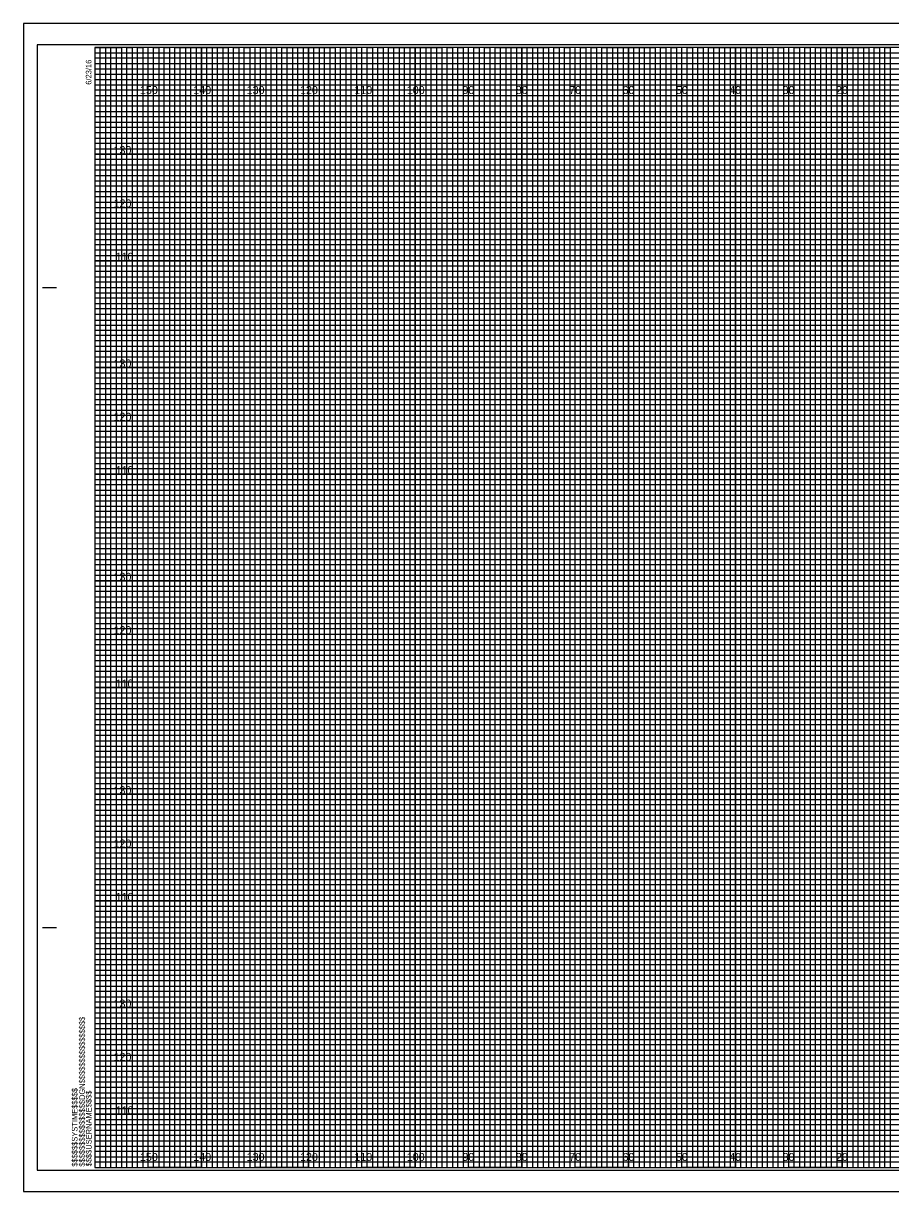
# Model space of a CAD drawing. Extents: x -13 to 323, y -5 to 654.
# Drawn here: x -13.4 to 149.1, y 215.5 to 434.5 of the extents above; entities that cross this region are included whole.
import ezdxf

# ---------------------------------------------------------------- set-up
doc = ezdxf.new("R2010")
doc.units = 0
for name, color, linetype in [('Prop XS Elevation Labels', 7, 'Continuous'), ('Prop XS Offset Labels', 7, 'Continuous'), ('Sheet Cross Section CELL', 7, 'Continuous'), ('Sheet Cross Section Grid Major CELL', 7, 'Continuous'), ('Sheet Cross Section Grid Middle CELL', 7, 'Continuous'), ('Sheet Cross Section Grid Minor 1 CELL', 7, 'Continuous'), ('Sheet Cross Section Grid Minor 2 CELL', 7, 'Continuous'), ('Sheet Cutting Line CELL', 7, 'Continuous'), ('Sheet DOT Grid CELL', 7, 'Continuous'), ('Sheet Plot Border Inside CELL', 7, 'Continuous'), ('Sheet Plot Border Outside CELL', 7, 'Continuous')]:
    doc.layers.add(name, color=color, linetype=linetype)

msp = doc.modelspace()

# ---------------------------------------------------------------- linework, layer by layer
at = {"layer": 'Sheet Cross Section CELL'}
for p, q in [((-9.8, 385), (-7.3, 385)), ((-9.7, 385), (-7.2, 385)), ((-9.8, 265), (-7.3, 265)), ((-9.7, 265), (-7.2, 265)), ((0, 220), (0, 220)), ((0, 220), (0, 220)), ((0, 220), (0, 220)), ((0, 220), (0, 220)), ((0, 220), (0, 220)), ((0, 220), (0, 220)), ((0, 220), (0, 220))]:
    msp.add_line(p, q, dxfattribs=at)
msp.add_lwpolyline([(320, 430), (0, 430), (0, 220), (320, 220)], close=True, dxfattribs=at)
at = {"layer": 'Sheet Cross Section Grid Major CELL'}
for p, q in [((10, 430), (0, 430)), ((10, 220), (10, 430)), ((30, 430), (20, 430)), ((20, 430), (20, 220)), ((30, 220), (30, 430)), ((50, 430), (40, 430)), ((40, 430), (40, 220)), ((50, 220), (50, 430)), ((70, 430), (60, 430)), ((60, 430), (60, 220)), ((70, 220), (70, 430)), ((90, 430), (80, 430)), ((80, 430), (80, 220)), ((90, 220), (90, 430)), ((110, 430), (100, 430)), ((100, 430), (100, 220)), ((110, 220), (110, 430)), ((130, 430), (120, 430)), ((120, 430), (120, 220)), ((130, 220), (130, 430)), ((150, 430), (140, 430)), ((140, 430), (140, 220)), ((20, 220), (10, 220)), ((40, 220), (30, 220)), ((60, 220), (50, 220)), ((80, 220), (70, 220)), ((100, 220), (90, 220)), ((120, 220), (110, 220)), ((140, 220), (130, 220))]:
    msp.add_line(p, q, dxfattribs=at)
for points in [[(0, 420), (320, 420), (320, 410), (0, 410)], [(0, 400), (320, 400), (320, 390), (0, 390)], [(0, 380), (320, 380), (320, 370), (0, 370)], [(0, 360), (320, 360), (320, 350), (0, 350)], [(0, 340), (320, 340), (320, 330), (0, 330)], [(0, 320), (320, 320), (320, 310), (0, 310)], [(0, 300), (320, 300), (320, 290), (0, 290)], [(0, 280), (320, 280), (320, 270), (0, 270)], [(0, 260), (320, 260), (320, 250), (0, 250)], [(0, 240), (320, 240), (320, 230), (0, 230)]]:
    msp.add_lwpolyline(points, dxfattribs=at)
at = {"layer": 'Sheet Cross Section Grid Middle CELL'}
for points in [[(0, 430), (5, 430), (5, 220), (15, 220), (15, 430), (25, 430), (25, 220), (35, 220), (35, 430), (45, 430), (45, 220), (55, 220), (55, 430), (65, 430), (65, 220), (75, 220), (75, 430), (85, 430), (85, 220), (95, 220), (95, 430), (105, 430), (105, 220), (115, 220), (115, 430), (125, 430), (125, 220), (135, 220), (135, 430), (145, 430), (145, 220), (155, 220)], [(0, 425), (275, 425)], [(0, 405), (320, 405), (320, 415), (0, 415)], [(0, 385), (320, 385), (320, 395), (0, 395)], [(0, 365), (320, 365), (320, 375), (0, 375)], [(0, 345), (320, 345), (320, 355), (0, 355)], [(0, 325), (320, 325), (320, 335), (0, 335)], [(0, 305), (320, 305), (320, 315), (0, 315)], [(0, 285), (320, 285), (320, 295), (0, 295)], [(0, 265), (320, 265), (320, 275), (0, 275)], [(0, 245), (320, 245), (320, 255), (0, 255)], [(0, 225), (320, 225), (320, 235), (0, 235)]]:
    msp.add_lwpolyline(points, dxfattribs=at)
at = {"layer": 'Sheet Cross Section Grid Minor 1 CELL'}
for p, q in [((0, 429), (260, 429)), ((260, 427.98), (0, 427.98)), ((0, 427.98), (0, 427)), ((0, 427), (260, 427)), ((260, 425.89), (0, 425.89)), ((0, 425.89), (0, 424)), ((0, 424), (320, 424))]:
    msp.add_line(p, q, dxfattribs=at)
for points in [[(0, 423), (270, 423), (320, 423), (320, 422), (0, 422)], [(0, 421), (320, 421), (320, 419), (0, 419)], [(0, 418), (320, 418), (320, 417), (0, 416.98)], [(0, 416), (320, 416), (320, 414), (0, 414)], [(0, 413), (320, 413), (320, 412), (0, 412)], [(0, 411), (320, 411), (320, 409), (0, 409)], [(0, 408), (320, 408), (320, 407), (0, 407)], [(0, 406), (320, 406), (320, 404), (0, 404)], [(0, 403), (320, 403), (320, 402), (0, 402)], [(0, 401), (320, 401), (320, 399), (0, 399)], [(0, 398), (320, 398), (320, 397), (0, 397)], [(0, 396), (320, 396), (320, 393.95), (320, 393), (320, 392), (0, 392)], [(0, 394), (320, 394), (320, 393), (0, 393)], [(0, 391), (320, 391), (320, 389), (0, 389.03)], [(0, 389.03), (320, 389), (320, 388), (0, 388)], [(0, 387), (320, 387), (320, 386), (0, 386)], [(0, 384), (320, 384), (320, 383), (0, 383)], [(0, 382), (320, 382), (320, 381), (0, 381)], [(-0.07, 378.89), (320, 378.89), (320, 377.88), (-0.07, 377.88)], [(0, 377), (320, 377), (320, 376), (0, 376)], [(0, 374), (320, 374), (320, 373), (0, 373)], [(0, 372), (320, 372), (320, 371), (0, 371)], [(0, 369), (320, 369), (320, 368), (0, 368)], [(0, 367), (320, 367), (320, 366), (0, 366)], [(0, 364), (320, 364), (320, 363), (0, 363)], [(0, 362), (320, 362), (320, 361), (0, 361)], [(0, 359), (320, 359), (319.99, 357.98), (0, 358)], [(0, 357), (320, 357), (320, 356), (0, 356)], [(0, 354), (320, 354), (320, 353), (0, 353)], [(0, 352), (320, 352), (320, 351), (0, 351)], [(0, 349), (320, 349), (320, 348), (0, 348)], [(0, 347), (320, 347), (320, 346), (0, 346)], [(0, 344), (320, 344), (320, 343), (0, 343)], [(0, 342), (320, 342), (320, 341), (0, 341)], [(0, 339), (320, 339), (320, 338), (0, 338)], [(0, 336.99), (320.07, 336.91), (320, 336), (0, 336)], [(0, 334), (320, 334), (320, 333), (0, 333)], [(0, 332), (320, 332), (320, 331), (0, 331)], [(0, 329), (320, 329), (320, 328), (0, 328)], [(0, 327), (320, 327), (320, 326), (0, 326)], [(0, 324), (320, 324), (320, 323), (0, 323)], [(0, 322), (320, 322), (320, 321), (0, 321)], [(0, 319), (320, 319), (320, 318), (0, 318)], [(0, 317), (320, 317), (320, 316), (0, 316)], [(0, 314), (320, 314), (320, 313), (0, 313)], [(0, 312), (320, 312), (320, 311), (0, 311)], [(0, 309), (320, 309), (320, 308), (0, 308)], [(0, 307), (320, 307), (320, 306), (0, 306)], [(0, 304), (320, 304), (320, 303), (0, 303)], [(0, 302), (320, 302), (320, 301), (0, 301)], [(0, 299), (320, 299), (319.99, 297.98), (0, 298)], [(0, 297), (320, 297), (320, 296), (0, 296)], [(0, 294), (320, 294), (320, 293), (0, 293)], [(0, 292), (320, 292), (320, 291), (0, 291)], [(0, 289), (320, 289), (320, 288), (0, 288)], [(0, 287), (320, 287), (320, 286), (0, 286)], [(0, 284), (320, 284), (320, 283), (0, 283)], [(0, 282), (320, 282), (320, 281), (0, 281)], [(0, 279), (320, 279), (320, 278), (0, 278)], [(0, 276.99), (320.07, 276.91), (320, 276), (0, 276)], [(0, 274), (320, 274), (320, 273), (0, 273)], [(0, 272), (320, 272), (320, 271), (0, 271)], [(0, 269), (320, 269), (320, 268), (0, 268)], [(0, 267), (320, 267), (320, 266), (0, 266)], [(0, 264), (320, 264), (320, 263), (0, 263)], [(0, 262), (320, 262), (320, 261), (0, 261)], [(0, 259), (320, 259), (320, 258), (0, 258)], [(0, 257), (320, 257), (320, 256), (0, 256)], [(0, 254), (320, 254), (320, 253), (0, 253)], [(0, 252), (320, 252), (320, 251), (0, 251)], [(0, 249), (320, 249), (320, 248), (0, 248)], [(0, 247), (320, 247), (320, 246), (0, 246)], [(0, 244), (320, 244), (320, 243), (0, 243)], [(0, 242), (320, 242), (320, 241), (0, 241)], [(0, 239), (320, 239), (320, 238), (0, 238)], [(0, 237), (320, 237), (320, 236), (0, 236)], [(0, 234), (320, 234), (320, 233), (0, 233)], [(0, 232), (320, 232), (320, 231), (0, 231)], [(0, 229), (320, 229), (320, 228), (0, 228)], [(0, 227), (320, 227), (320, 226), (0, 226)], [(0, 224), (320, 224), (320, 223), (0, 223)], [(0, 222), (320, 222), (320, 221), (0, 221)]]:
    msp.add_lwpolyline(points, dxfattribs=at)
at = {"layer": 'Sheet Cross Section Grid Minor 2 CELL'}
for points in [[(0, 220), (1, 220), (1, 430), (2, 430), (2, 220)], [(2, 220), (3, 220), (3, 430), (4, 430), (4, 220)], [(5, 220), (6, 220), (6, 430), (7, 430), (7, 220)], [(7, 220), (8, 220), (8, 430), (9, 430), (9, 220)], [(10, 220), (11, 220), (11, 430), (12, 430), (12, 220)], [(12, 220), (13, 220), (13, 430), (14, 430), (14, 220)], [(15, 220), (16, 220), (16, 430), (17, 430), (17, 220)], [(17, 220), (18, 220), (18, 430), (19, 430), (19, 220)], [(20, 220), (21, 220), (21, 430), (22, 430), (22, 220)], [(22, 220), (23, 220), (23, 430), (24, 430), (24, 220)], [(25, 220), (26, 220), (26, 430), (27, 430), (27, 220)], [(27, 220), (28, 220), (28, 430), (29, 430), (29, 220)], [(30, 220), (31, 220), (31, 430), (32, 430), (32, 220)], [(32, 220), (33, 220), (33, 430), (34, 430), (34, 220)], [(35, 220), (36, 220), (36, 430), (37, 430), (37, 220)], [(37, 220), (38, 220), (38, 430), (39, 430), (39, 220)], [(40, 220), (41, 220), (41, 430), (42, 430), (42, 220)], [(42, 220), (43, 220), (43, 430), (44, 430), (44, 220)], [(45, 220), (46, 220), (46, 430), (47, 430), (47, 220)], [(47, 220), (48, 220), (48, 430), (49, 430), (49, 220)], [(50, 220), (51, 220), (51, 430), (52, 430), (52, 220)], [(52, 220), (53, 220), (53, 430), (54, 430), (54, 220)], [(55, 220), (56, 220), (56, 430), (57, 430), (57, 220)], [(57, 220), (58, 220), (58, 430), (59, 430), (59, 220)], [(60, 220), (61, 220), (61, 430), (62, 430), (62, 220)], [(62, 220), (63, 220), (63, 430), (64, 430), (64, 220)], [(65, 220), (66, 220), (66, 430), (67, 430), (67, 220)], [(67, 220), (68, 220), (68, 430), (69, 430), (69, 220)], [(70, 220), (71, 220), (71, 430), (72, 430), (72, 220)], [(72, 220), (73, 220), (73, 430), (74, 430), (74, 220)], [(75, 220), (76, 220), (76, 430), (77, 430), (77, 220)], [(77, 220), (78, 220), (78, 430), (79, 430), (79, 220)], [(80, 220), (81, 220), (81, 430), (82, 430), (82, 220)], [(82, 220), (83, 220), (83, 430), (84, 430), (84, 220)], [(85, 220), (86, 220), (86, 430), (87, 430), (87, 220)], [(87, 220), (88, 220), (88, 430), (89, 430), (89, 220)], [(90, 220), (91, 220), (91, 430), (92, 430), (92, 220)], [(92, 220), (93, 220), (93, 430), (94, 430), (94, 220)], [(95, 220), (96, 220), (96, 430), (97, 430), (97, 220)], [(97, 220), (98, 220), (98, 430), (99, 430), (99, 220)], [(100, 220), (101, 220), (101, 430), (102, 430), (102, 220)], [(102, 220), (103, 220), (103, 430), (104, 430), (104, 220)], [(105, 220), (106, 220), (106, 430), (107, 430), (107, 220)], [(107, 220), (108, 220), (108, 430), (109, 430), (109, 220)], [(110, 220), (111, 220), (111, 430), (112, 430), (112, 220)], [(112, 220), (113, 220), (113, 430), (114, 430), (114, 220)], [(115, 220), (116, 220), (116, 430), (117, 430), (117, 220)], [(117, 220), (118, 220), (118, 430), (119, 430), (119, 220)], [(120, 220), (121, 220), (121, 430), (122, 430), (122, 220)], [(122, 220), (123, 220), (123, 430), (124, 430), (124, 220)], [(125, 220), (126, 220), (126, 430), (127, 430), (127, 220)], [(127, 220), (128, 220), (128, 430), (129, 430), (129, 220)], [(130, 220), (131, 220), (131, 430), (132, 430), (132, 220)], [(132, 220), (133, 220), (133, 430), (134, 430), (134, 220)], [(135, 220), (136, 220), (136, 430), (137, 430), (137, 220)], [(137, 220), (138, 220), (138, 430), (139, 430), (139, 220)], [(140, 220), (141, 220), (141, 430), (142, 430), (142, 220)], [(142, 220), (143, 220), (143, 430), (144, 430), (144, 220)], [(145, 220), (146, 220), (146, 430), (147, 430), (147, 220)], [(147, 220), (148, 220), (148, 430), (149, 430), (149, 220)]]:
    msp.add_lwpolyline(points, dxfattribs=at)
at = {"layer": 'Sheet Cutting Line CELL'}
for p, q in [((323.3, 434.5), (-13.4, 434.5)), ((-13.4, 434.5), (-13.4, 215.5)), ((-13.4, 215.5), (323.3, 215.5))]:
    msp.add_line(p, q, dxfattribs=at)
at = {"layer": 'Sheet DOT Grid CELL'}
for p, q in [((10, 220), (10, 430)), ((20, 220), (20, 430)), ((30, 220), (30, 430)), ((40, 220), (40, 430)), ((50, 220), (50, 430)), ((60, 220), (60, 430)), ((70, 220), (70, 430)), ((80, 220), (80, 430)), ((90, 220), (90, 430)), ((100, 220), (100, 430)), ((110, 220), (110, 430)), ((120, 220), (120, 430)), ((130, 220), (130, 430)), ((140, 220), (140, 430)), ((0, 420), (320, 420)), ((0, 410), (320, 410)), ((0, 400), (320, 400)), ((0, 390), (320, 390)), ((0, 380), (320, 380)), ((0, 370), (320, 370)), ((0, 360), (320, 360)), ((0, 350), (320, 350)), ((0, 340), (320, 340)), ((0, 330), (320, 330)), ((0, 320), (320, 320)), ((0, 310), (320, 310)), ((0, 300), (320, 300)), ((0, 290), (320, 290)), ((0, 280), (320, 280)), ((0, 270), (320, 270)), ((0, 260), (320, 260)), ((0, 250), (320, 250)), ((0, 240), (320, 240)), ((0, 230), (320, 230))]:
    msp.add_line(p, q, dxfattribs=at)
at = {"layer": 'Sheet Plot Border Inside CELL'}
msp.add_lwpolyline([(-10.8, 219.5), (322.4, 219.5), (322.4, 430.5), (-10.8, 430.5)], close=True, dxfattribs=at)
at = {"layer": 'Sheet Plot Border Outside CELL'}
msp.add_lwpolyline([(-13.4, 215.5), (323.3, 215.5), (323.3, 434.5), (-13.4, 434.5)], close=True, dxfattribs=at)

# ---------------------------------------------------------------- texts
at = {"layer": 'Prop XS Elevation Labels'}
for s, p in [('130', (3.49, 410)), ('120', (3.5, 400)), ('110', (3.88, 390)), ('130', (3.49, 370)), ('120', (3.5, 360)), ('110', (3.88, 350)), ('130', (3.49, 330)), ('120', (3.5, 320)), ('110', (3.88, 310)), ('130', (3.49, 290)), ('120', (3.5, 280)), ('110', (3.88, 270)), ('130', (3.49, 250)), ('120', (3.5, 240)), ('110', (3.88, 230))]:
    msp.add_text(s, height=1.5, dxfattribs=at).set_placement(p)
at = {"layer": 'Prop XS Offset Labels'}
for s, p in [('150', (8.44, 421.25)), ('140', (18.44, 421.25)), ('130', (28.44, 421.25)), ('120', (38.44, 421.25)), ('110', (48.62, 421.25)), ('100', (58.44, 421.25)), ('90', (68.86, 421.25)), ('80', (78.86, 421.25)), ('70', (88.86, 421.25)), ('60', (98.86, 421.25)), ('50', (108.86, 421.25)), ('40', (118.86, 421.25)), ('30', (128.86, 421.25)), ('20', (138.86, 421.25)), ('150', (8.44, 221.25)), ('140', (18.44, 221.25)), ('130', (28.44, 221.25)), ('120', (38.44, 221.25)), ('110', (48.62, 221.25)), ('100', (58.44, 221.25)), ('90', (68.86, 221.25)), ('80', (78.86, 221.25)), ('70', (88.86, 221.25)), ('60', (98.86, 221.25)), ('50', (108.86, 221.25)), ('40', (118.86, 221.25)), ('30', (128.86, 221.25)), ('20', (138.86, 221.25))]:
    msp.add_text(s, height=1.5, dxfattribs=at).set_placement(p)
at = {"layer": 'Sheet Cross Section CELL'}
for s, p in [('6/23/16', (-0.65, 423)), ('$$$$$$$$$$$$$$$$DGN$$$$$$$$$$$$$$$$', (-1.88, 220.18)), ('$$$$$$SYSTIME$$$$$', (-3.26, 220.18)), ('$$$$USERNAME$$$$', (-0.62, 220.23))]:
    msp.add_text(s, height=1.05, rotation=90, dxfattribs=at).set_placement(p)

doc.saveas('drawing.dxf')
